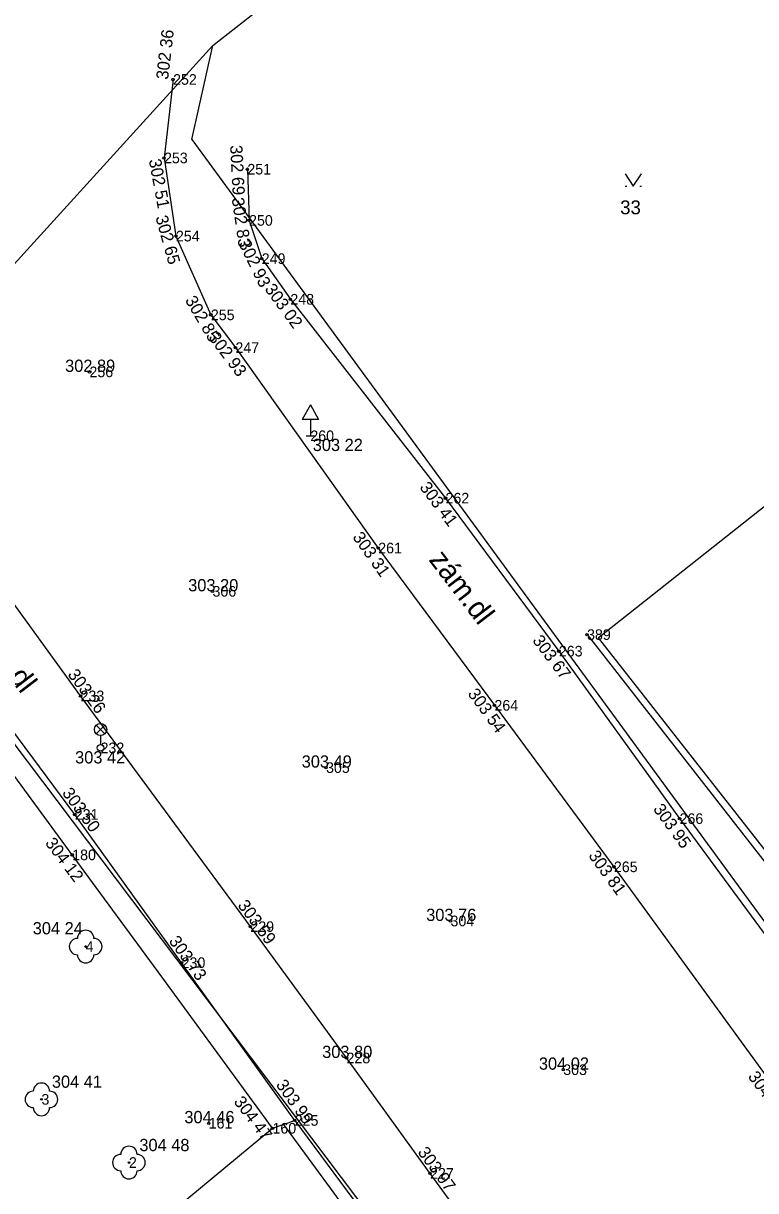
# Model space of a CAD drawing. Extents: x -492811 to -492366, y -1127107 to -1126748.
# Drawn here: x -492659.56 to -492641.63, y -1126887.82 to -1126859.24 of the extents above; entities that cross this region are included whole.
import ezdxf

# ---------------------------------------------------------------- set-up
doc = ezdxf.new("R2010")
doc.units = 0
for name, color, linetype in [('body', 7, 'Continuous'), ('doprava', 7, 'Continuous'), ('katastrální mapa', 7, 'Continuous'), ('oplocení', 7, 'Continuous'), ('podrobný výškový bod', 7, 'Continuous'), ('popis ploch', 7, 'Continuous'), ('rozhraní ploch', 7, 'Continuous'), ('stavební objekt', 7, 'Continuous'), ('stromy', 7, 'Continuous'), ('veřejné osvětlení', 7, 'Continuous'), ('vstup na pozemek', 7, 'Continuous'), ('výšky', 7, 'Continuous'), ('čísla bodů', 7, 'Continuous')]:
    doc.layers.add(name, color=color, linetype=linetype)

msp = doc.modelspace()

# ---------------------------------------------------------------- linework, layer by layer
at = {"layer": 'body'}
for p, q in [((-492655.892, -1126860.619), (-492655.892, -1126860.619)), ((-492656.114, -1126862.54), (-492656.114, -1126862.54)), ((-492654.075, -1126862.816), (-492654.075, -1126862.816)), ((-492654.033, -1126864.069), (-492654.033, -1126864.069)), ((-492655.823, -1126864.454), (-492655.823, -1126864.454)), ((-492653.722, -1126865.006), (-492653.722, -1126865.006)), ((-492653.022, -1126866), (-492653.022, -1126866)), ((-492654.968, -1126866.382), (-492654.968, -1126866.382)), ((-492654.366, -1126867.185), (-492654.366, -1126867.185)), ((-492657.939, -1126867.778), (-492657.939, -1126867.778)), ((-492652.533, -1126869.343), (-492652.533, -1126869.343)), ((-492649.225, -1126870.87), (-492649.225, -1126870.87)), ((-492650.872, -1126872.091), (-492650.872, -1126872.091)), ((-492654.927, -1126873.151), (-492654.927, -1126873.151)), ((-492645.761, -1126874.211), (-492645.761, -1126874.211)), ((-492646.451, -1126874.616), (-492646.451, -1126874.616)), ((-492658.157, -1126875.711), (-492658.157, -1126875.711)), ((-492648.027, -1126875.942), (-492648.027, -1126875.942)), ((-492657.667, -1126876.984), (-492657.667, -1126876.984)), ((-492652.149, -1126877.467), (-492652.149, -1126877.467)), ((-492658.298, -1126878.614), (-492658.298, -1126878.614)), ((-492643.497, -1126878.716), (-492643.497, -1126878.716)), ((-492658.361, -1126879.603), (-492658.361, -1126879.603)), ((-492645.104, -1126879.896), (-492645.104, -1126879.896)), ((-492654.001, -1126881.36), (-492654.001, -1126881.36)), ((-492649.102, -1126881.221), (-492649.102, -1126881.221)), ((-492658.032, -1126881.848), (-492658.032, -1126881.848)), ((-492655.683, -1126882.243), (-492655.683, -1126882.243)), ((-492651.648, -1126884.576), (-492651.648, -1126884.576)), ((-492646.344, -1126884.863), (-492646.344, -1126884.863)), ((-492659.114, -1126885.589), (-492659.114, -1126885.589)), ((-492655.021, -1126886.173), (-492655.021, -1126886.173)), ((-492652.915, -1126886.104), (-492652.915, -1126886.104)), ((-492653.46, -1126886.297), (-492653.46, -1126886.297)), ((-492656.973, -1126887.136), (-492656.973, -1126887.136)), ((-492649.603, -1126887.401), (-492649.603, -1126887.401))]:
    msp.add_line(p, q, dxfattribs=at)
at = {"layer": 'doprava'}
for p, q in [((-492652.533, -1126868.583), (-492652.733, -1126868.943)), ((-492652.533, -1126868.583), (-492652.333, -1126868.943)), ((-492652.333, -1126868.943), (-492652.733, -1126868.943)), ((-492652.533, -1126868.943), (-492652.533, -1126869.343)), ((-492652.633, -1126869.343), (-492652.433, -1126869.343))]:
    msp.add_line(p, q, dxfattribs=at)
at = {"layer": 'katastrální mapa'}
for p, q in [((-492654.92, -1126859.79), (-492643.59, -1126850.87)), ((-492664.63, -1126870.47), (-492654.92, -1126859.79)), ((-492655.43, -1126862.09), (-492654.92, -1126859.79)), ((-492655.43, -1126862.09), (-492637.39, -1126886.75)), ((-492644.83, -1126862.93), (-492644.63, -1126863.23)), ((-492644.63, -1126863.23), (-492644.43, -1126862.93)), ((-492644.83, -1126863.23), (-492644.79, -1126863.23)), ((-492644.47, -1126863.23), (-492644.43, -1126863.23)), ((-492645.49, -1126874.29), (-492635.79, -1126866.61)), ((-492664.63, -1126870.47), (-492648.16, -1126892.3)), ((-492645.49, -1126874.29), (-492637.3, -1126884.74))]:
    msp.add_line(p, q, dxfattribs=at)
at = {"layer": 'oplocení'}
for p, q in [((-492658.298, -1126878.614), (-492663.17, -1126872.055)), ((-492658.361, -1126879.603), (-492663.663, -1126872.372)), ((-492655.683, -1126882.243), (-492658.298, -1126878.614)), ((-492656.171, -1126882.593), (-492658.361, -1126879.603)), ((-492652.915, -1126886.104), (-492655.683, -1126882.243)), ((-492653.46, -1126886.297), (-492656.171, -1126882.593)), ((-492653.46, -1126886.297), (-492652.915, -1126886.104))]:
    msp.add_line(p, q, dxfattribs=at)
at = {"layer": 'podrobný výškový bod'}
for centre in [(-492655.892, -1126860.619), (-492656.114, -1126862.54), (-492654.075, -1126862.816), (-492654.033, -1126864.069), (-492655.823, -1126864.454), (-492653.722, -1126865.006), (-492653.022, -1126866), (-492654.968, -1126866.382), (-492654.366, -1126867.185), (-492657.939, -1126867.778), (-492649.225, -1126870.87), (-492650.872, -1126872.091), (-492654.927, -1126873.151), (-492645.761, -1126874.211), (-492646.451, -1126874.616), (-492658.157, -1126875.711), (-492648.027, -1126875.942), (-492652.149, -1126877.467), (-492658.298, -1126878.614), (-492643.497, -1126878.716), (-492658.361, -1126879.603), (-492645.104, -1126879.896), (-492654.001, -1126881.36), (-492649.102, -1126881.221), (-492655.683, -1126882.243), (-492651.648, -1126884.576), (-492646.344, -1126884.863), (-492655.021, -1126886.173), (-492652.915, -1126886.104), (-492653.46, -1126886.297), (-492649.603, -1126887.401)]:
    msp.add_circle(centre, 0.03, dxfattribs=at)
at = {"layer": 'rozhraní ploch'}
for p, q in [((-492655.892, -1126860.619), (-492656.114, -1126862.54)), ((-492656.114, -1126862.54), (-492655.823, -1126864.454)), ((-492654.075, -1126862.816), (-492654.033, -1126864.069)), ((-492654.033, -1126864.069), (-492653.722, -1126865.006)), ((-492655.823, -1126864.454), (-492654.968, -1126866.382)), ((-492653.722, -1126865.006), (-492653.022, -1126866)), ((-492653.022, -1126866), (-492649.225, -1126870.87)), ((-492654.968, -1126866.382), (-492654.366, -1126867.185)), ((-492654.366, -1126867.185), (-492650.872, -1126872.091)), ((-492649.225, -1126870.87), (-492646.451, -1126874.616)), ((-492650.872, -1126872.091), (-492648.027, -1126875.942)), ((-492658.157, -1126875.711), (-492660.631, -1126872.299)), ((-492646.451, -1126874.616), (-492643.497, -1126878.716)), ((-492654.001, -1126881.36), (-492658.157, -1126875.711)), ((-492648.027, -1126875.942), (-492645.104, -1126879.896)), ((-492643.497, -1126878.716), (-492639.731, -1126883.839)), ((-492645.104, -1126879.896), (-492641.178, -1126885.289)), ((-492651.648, -1126884.576), (-492654.001, -1126881.36)), ((-492649.603, -1126887.401), (-492651.648, -1126884.576)), ((-492652.915, -1126886.104), (-492650.834, -1126888.907)), ((-492657.682, -1126889.789), (-492653.46, -1126886.297)), ((-492644.056, -1126894.975), (-492649.603, -1126887.401))]:
    msp.add_line(p, q, dxfattribs=at)
at = {"layer": 'stavební objekt'}
msp.add_line((-492645.761, -1126874.211), (-492637.398, -1126884.917), dxfattribs=at)
at = {"layer": 'stromy'}
for centre in [(-492658.032, -1126881.848), (-492659.114, -1126885.589), (-492656.973, -1126887.136)]:
    msp.add_circle(centre, 0.02, dxfattribs=at)
for centre, start, end in [((-492658.232, -1126881.848), 90, 270), ((-492658.032, -1126881.648), 360, 180), ((-492657.832, -1126881.848), 270, 90), ((-492658.032, -1126882.048), 180, 0), ((-492659.314, -1126885.589), 90, 270), ((-492659.114, -1126885.389), 360, 180), ((-492658.914, -1126885.589), 270, 90), ((-492659.114, -1126885.789), 180, 0), ((-492656.973, -1126886.936), 360, 180), ((-492657.173, -1126887.136), 90, 270), ((-492656.773, -1126887.136), 270, 90), ((-492656.973, -1126887.336), 180, 0)]:
    msp.add_arc(centre, 0.2, start, end, dxfattribs=at)
at = {"layer": 'veřejné osvětlení'}
for p, q in [((-492657.773, -1126876.64), (-492657.561, -1126876.428)), ((-492657.773, -1126876.428), (-492657.561, -1126876.64)), ((-492657.667, -1126876.684), (-492657.667, -1126876.904))]:
    msp.add_line(p, q, dxfattribs=at)
for centre, radius in [((-492657.667, -1126876.534), 0.15), ((-492657.667, -1126876.984), 0.08)]:
    msp.add_circle(centre, radius, dxfattribs=at)
at = {"layer": 'vstup na pozemek'}
msp.add_line((-492653.188, -1126886.201), (-492651.074, -1126889.087), dxfattribs=at)

# ---------------------------------------------------------------- texts
at = {"layer": 'katastrální mapa'}
msp.add_text('33', height=0.34, dxfattribs=at).set_placement((-492644.95, -1126863.92))
at = {"layer": 'popis ploch'}
for p in [(-492649.65, -1126872.383), (-492660.845, -1126874.058)]:
    msp.add_text('zám.dl', height=0.52, rotation=307.4503, dxfattribs=at).set_placement(p)
at = {"layer": 'výšky'}
for s, rotation, p in [('302 36 ', 83.2666, (-492656.015, -1126860.633)), ('302 69 ', 272.9634, (-492654.497, -1126862.233)), ('302 51 ', 280.4541, (-492656.487, -1126862.59)), ('302 83 ', 278.2985, (-492654.458, -1126863.531)), ('302 65 ', 285.5632, (-492656.327, -1126863.991)), ('302 93 ', 296.0097, (-492654.295, -1126864.637)), ('303 02 ', 306.0435, (-492653.664, -1126865.751)), ('302 85 ', 300.4641, (-492655.609, -1126866.022)), ('302 93 ', 306.8341, (-492655.041, -1126866.941)), ('303 41 ', 306.4944, (-492649.873, -1126870.606)), ('303 31 ', 305.1929, (-492651.512, -1126871.825)), ('303 67 ', 306.9736, (-492647.112, -1126874.358)), ('303 26 ', 306.5647, (-492658.486, -1126875.189)), ('303 54 ', 306.1678, (-492648.694, -1126875.66)), ('303 50 ', 306.3681, (-492658.622, -1126878.091)), ('303 95 ', 306.0069, (-492644.155, -1126878.483)), ('304 12 ', 307.015, (-492659.038, -1126879.318)), ('303 81 ', 305.8802, (-492645.74, -1126879.625)), ('303 59 ', 306.767, (-492654.326, -1126880.842)), ('303 73 ', 305.8547, (-492656.009, -1126881.716)), ('303 99 ', 305.4415, (-492653.388, -1126885.233)), ('304 16 ', 306.2485, (-492641.836, -1126885.033)), ('304 47 ', 307.0506, (-492654.422, -1126885.649)), ('303 97 ', 306.0208, (-492649.919, -1126886.884))]:
    msp.add_text(s, height=0.3, rotation=rotation, dxfattribs=at).set_placement(p)
for s, p in [('302 89 ', (-492658.535, -1126867.778)), ('303 22 ', (-492652.475, -1126869.716)), ('303 20 ', (-492655.523, -1126873.151)), ('303 42 ', (-492658.291, -1126877.365)), ('303 49 ', (-492652.745, -1126877.467)), ('303 76 ', (-492649.698, -1126881.221)), ('304 24 ', (-492659.328, -1126881.549)), ('303 80 ', (-492652.244, -1126884.576)), ('304 02 ', (-492646.94, -1126884.863)), ('304 41 ', (-492658.859, -1126885.305)), ('304 46 ', (-492655.617, -1126886.173)), ('304 48 ', (-492656.718, -1126886.857))]:
    msp.add_text(s, height=0.3, dxfattribs=at).set_placement(p)
at = {"layer": 'čísla bodů'}
for s, p in [('252', (-492655.892, -1126860.749)), ('253', (-492656.114, -1126862.67)), ('251', (-492654.075, -1126862.946)), ('250', (-492654.033, -1126864.199)), ('254', (-492655.823, -1126864.584)), ('249', (-492653.722, -1126865.136)), ('248', (-492653.022, -1126866.13)), ('255', (-492654.968, -1126866.512)), ('247', (-492654.366, -1126867.315)), ('256', (-492657.939, -1126867.908)), ('260', (-492652.533, -1126869.473)), ('262', (-492649.225, -1126871)), ('261', (-492650.872, -1126872.221)), ('306', (-492654.927, -1126873.281)), ('389', (-492645.761, -1126874.341)), ('263', (-492646.451, -1126874.746)), ('233', (-492658.157, -1126875.841)), ('264', (-492648.027, -1126876.072)), ('232', (-492657.667, -1126877.114)), ('305', (-492652.149, -1126877.597)), ('231', (-492658.298, -1126878.744)), ('266', (-492643.497, -1126878.846)), ('180', (-492658.361, -1126879.733)), ('265', (-492645.104, -1126880.026)), ('304', (-492649.102, -1126881.351)), ('229', (-492654.001, -1126881.49)), ('4', (-492658.032, -1126881.978)), ('230', (-492655.683, -1126882.373)), ('228', (-492651.648, -1126884.706)), ('303', (-492646.344, -1126884.993)), ('3', (-492659.114, -1126885.719)), ('225', (-492652.915, -1126886.234)), ('161', (-492655.021, -1126886.303)), ('160', (-492653.46, -1126886.427)), ('2', (-492656.973, -1126887.266)), ('227', (-492649.603, -1126887.531))]:
    msp.add_text(s, height=0.26, dxfattribs=at).set_placement(p)

doc.saveas('drawing.dxf')
